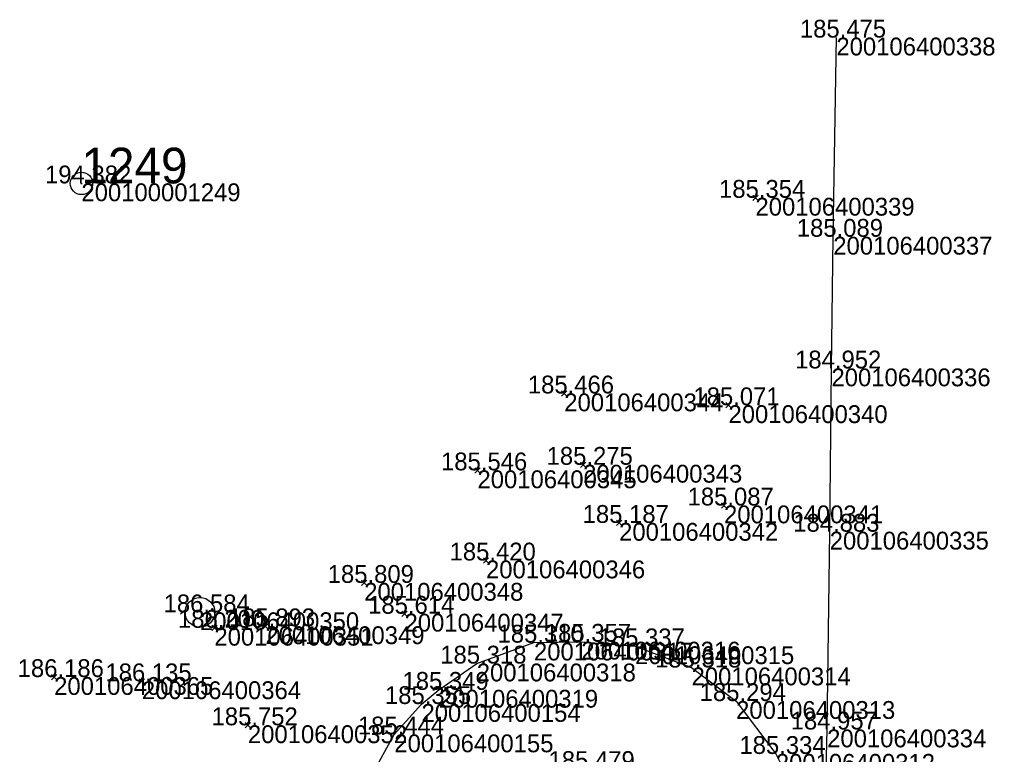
# Model space of a CAD drawing. Extents: x -601392 to -601237, y -1181159 to -1180628.
# Drawn here: x -601309.3 to -601243.7, y -1180894 to -1180844.6 of the extents above; entities that cross this region are included whole.
import ezdxf

# ---------------------------------------------------------------- set-up
doc = ezdxf.new("R2010")
doc.units = 0
for name, color, linetype in [('OMP', 7, 'Continuous'), ('Vrstva 16', 7, 'Continuous'), ('Vrstva 17', 7, 'Continuous'), ('Vrstva 43', 7, 'Continuous'), ('Vrstva 49', 7, 'Continuous'), ('Vrstva 61', 7, 'Continuous'), ('Vzdy červené', 7, 'Continuous')]:
    doc.layers.add(name, color=color, linetype=linetype)

msp = doc.modelspace()

# ---------------------------------------------------------------- linework, layer by layer
at = {"layer": 'OMP'}
for p, q in [((-601254.315, -1180845.801), (-601254.315, -1180845.801)), ((-601305.117, -1180855.611), (-601305.117, -1180855.611)), ((-601259.76, -1180856.581), (-601259.76, -1180856.581)), ((-601254.524, -1180859.204), (-601254.524, -1180859.204)), ((-601254.646, -1180868.066), (-601254.646, -1180868.066)), ((-601272.625, -1180869.748), (-601272.625, -1180869.748)), ((-601261.578, -1180870.541), (-601261.578, -1180870.541)), ((-601271.358, -1180874.549), (-601271.358, -1180874.549)), ((-601278.467, -1180874.924), (-601278.467, -1180874.924)), ((-601261.876, -1180877.287), (-601261.876, -1180877.287)), ((-601268.937, -1180878.459), (-601268.937, -1180878.459)), ((-601254.764, -1180879.051), (-601254.764, -1180879.051)), ((-601277.892, -1180880.989), (-601277.892, -1180880.989)), ((-601286.089, -1180882.496), (-601286.089, -1180882.496)), ((-601297.139, -1180884.477), (-601297.139, -1180884.477)), ((-601283.374, -1180884.571), (-601283.374, -1180884.571)), ((-601296.169, -1180885.517), (-601296.169, -1180885.517)), ((-601292.741, -1180885.417), (-601292.741, -1180885.417)), ((-601274.665, -1180886.517), (-601274.665, -1180886.517)), ((-601271.48, -1180886.455), (-601271.48, -1180886.455)), ((-601267.861, -1180886.763), (-601267.861, -1180886.763)), ((-601278.515, -1180887.924), (-601278.515, -1180887.924)), ((-601264.06, -1180888.189), (-601264.06, -1180888.189)), ((-601306.954, -1180888.833), (-601306.954, -1180888.833)), ((-601301.046, -1180889.118), (-601301.046, -1180889.118)), ((-601281.058, -1180889.692), (-601281.058, -1180889.692)), ((-601261.063, -1180890.448), (-601261.063, -1180890.448)), ((-601282.236, -1180890.646), (-601282.236, -1180890.646)), ((-601293.913, -1180892.078), (-601293.913, -1180892.078)), ((-601254.937, -1180892.361), (-601254.937, -1180892.361)), ((-601284.062, -1180892.694), (-601284.062, -1180892.694)), ((-601258.39, -1180894.006), (-601258.39, -1180894.006))]:
    msp.add_line(p, q, dxfattribs=at)
at = {"layer": 'Vrstva 16'}
msp.add_lwpolyline([(-601285.564, -1180895.44), (-601284.062, -1180892.694), (-601282.236, -1180890.646), (-601281.058, -1180889.692), (-601278.515, -1180887.924), (-601274.665, -1180886.517), (-601271.48, -1180886.455), (-601267.861, -1180886.763), (-601264.06, -1180888.189), (-601261.063, -1180890.448), (-601258.39, -1180894.006), (-601257.215, -1180896.343)], dxfattribs=at)
at = {"layer": 'Vrstva 17'}
msp.add_lwpolyline([(-601255.195, -1180903.174), (-601254.937, -1180892.361), (-601254.764, -1180879.051), (-601254.646, -1180868.066), (-601254.524, -1180859.204), (-601254.315, -1180845.801)], dxfattribs=at)
at = {"layer": 'Vrstva 43'}
msp.add_circle((-601297.139, -1180884.477), 1, dxfattribs=at)
at = {"layer": 'Vrstva 49'}
for p, q in [((-601259.937, -1180856.404), (-601259.583, -1180856.758)), ((-601259.937, -1180856.758), (-601259.583, -1180856.404)), ((-601272.802, -1180869.571), (-601272.448, -1180869.925)), ((-601272.802, -1180869.925), (-601272.448, -1180869.571)), ((-601261.755, -1180870.364), (-601261.401, -1180870.718)), ((-601261.755, -1180870.718), (-601261.401, -1180870.364)), ((-601278.644, -1180874.747), (-601278.29, -1180875.101)), ((-601278.644, -1180875.101), (-601278.29, -1180874.747)), ((-601271.535, -1180874.372), (-601271.181, -1180874.726)), ((-601271.535, -1180874.726), (-601271.181, -1180874.372)), ((-601262.053, -1180877.11), (-601261.699, -1180877.464)), ((-601262.053, -1180877.464), (-601261.699, -1180877.11)), ((-601269.114, -1180878.282), (-601268.76, -1180878.636)), ((-601269.114, -1180878.636), (-601268.76, -1180878.282)), ((-601278.069, -1180880.812), (-601277.715, -1180881.166)), ((-601278.069, -1180881.166), (-601277.715, -1180880.812)), ((-601286.266, -1180882.319), (-601285.912, -1180882.673)), ((-601286.266, -1180882.673), (-601285.912, -1180882.319)), ((-601283.551, -1180884.394), (-601283.197, -1180884.748)), ((-601283.551, -1180884.748), (-601283.197, -1180884.394)), ((-601292.918, -1180885.24), (-601292.564, -1180885.594)), ((-601292.918, -1180885.594), (-601292.564, -1180885.24)), ((-601296.346, -1180885.34), (-601295.992, -1180885.694)), ((-601296.346, -1180885.694), (-601295.992, -1180885.34)), ((-601307.131, -1180888.656), (-601306.777, -1180889.01)), ((-601307.131, -1180889.01), (-601306.777, -1180888.656)), ((-601301.223, -1180888.941), (-601300.869, -1180889.295)), ((-601301.223, -1180889.295), (-601300.869, -1180888.941)), ((-601294.09, -1180891.901), (-601293.736, -1180892.255)), ((-601294.09, -1180892.255), (-601293.736, -1180891.901))]:
    msp.add_line(p, q, dxfattribs=at)
at = {"layer": 'Vzdy červené'}
msp.add_line((-601305.167, -1180855.611), (-601305.067, -1180855.611), dxfattribs=at)
msp.add_circle((-601305.117, -1180855.611), 0.756, dxfattribs=at)

# ---------------------------------------------------------------- texts
at = {"layer": 'OMP'}
for s, p in [('200106400338', (-601254.315, -1180847.001)), ('200100001249', (-601305.117, -1180856.811)), ('200106400339', (-601259.76, -1180857.781)), ('200106400337', (-601254.524, -1180860.404)), ('200106400336', (-601254.646, -1180869.266)), ('200106400344', (-601272.625, -1180870.948)), ('200106400340', (-601261.578, -1180871.741)), ('200106400343', (-601271.358, -1180875.749)), ('200106400345', (-601278.467, -1180876.124)), ('200106400341', (-601261.876, -1180878.487)), ('200106400342', (-601268.937, -1180879.659)), ('200106400335', (-601254.764, -1180880.251)), ('200106400346', (-601277.892, -1180882.189)), ('200106400348', (-601286.089, -1180883.696)), ('200106400350', (-601297.139, -1180885.677)), ('200106400347', (-601283.374, -1180885.771)), ('200106400351', (-601296.169, -1180886.717)), ('200106400349', (-601292.741, -1180886.617)), ('200106400317', (-601274.665, -1180887.717)), ('200106400316', (-601271.48, -1180887.655)), ('200106400315', (-601267.861, -1180887.963)), ('200106400318', (-601278.515, -1180889.124)), ('200106400314', (-601264.06, -1180889.389)), ('200106400365', (-601306.954, -1180890.033)), ('200106400364', (-601301.046, -1180890.318)), ('200106400319', (-601281.058, -1180890.892)), ('200106400313', (-601261.063, -1180891.648)), ('200106400154', (-601282.236, -1180891.846)), ('200106400352', (-601293.913, -1180893.278)), ('200106400334', (-601254.937, -1180893.561)), ('200106400155', (-601284.062, -1180893.894)), ('200106400312', (-601258.39, -1180895.206))]:
    msp.add_text(s, height=1.2, dxfattribs=at).set_placement(p)
at = {"layer": 'Vrstva 61'}
for s, p in [('185.475', (-601256.771, -1180845.801)), ('194.382', (-601307.565, -1180855.611)), ('185.354', (-601262.211, -1180856.581)), ('185.089', (-601256.978, -1180859.204)), ('184.952', (-601257.094, -1180868.066)), ('185.466', (-601275.077, -1180869.748)), ('185.071', (-601263.935, -1180870.541)), ('185.275', (-601273.814, -1180874.549)), ('185.546', (-601280.919, -1180874.924)), ('185.087', (-601264.328, -1180877.287)), ('185.187', (-601271.389, -1180878.459)), ('184.883', (-601257.216, -1180879.051)), ('185.420', (-601280.343, -1180880.989)), ('185.809', (-601288.543, -1180882.496)), ('186.584', (-601299.59, -1180884.477)), ('185.614', (-601285.825, -1180884.571)), ('186.200', (-601298.62, -1180885.517)), ('185.893', (-601295.193, -1180885.417)), ('185.310', (-601277.116, -1180886.517)), ('185.357', (-601273.932, -1180886.455)), ('185.337', (-601270.313, -1180886.763)), ('185.318', (-601280.969, -1180887.924)), ('185.318', (-601266.514, -1180888.189)), ('186.186', (-601309.406, -1180888.833)), ('186.135', (-601303.502, -1180889.118)), ('185.349', (-601283.512, -1180889.692)), ('185.294', (-601263.514, -1180890.448)), ('185.355', (-601284.692, -1180890.646)), ('185.752', (-601296.361, -1180892.078)), ('184.957', (-601257.389, -1180892.361)), ('185.444', (-601286.513, -1180892.694)), ('185.334', (-601260.841, -1180894.006)), ('185.479', (-601273.685, -1180895.02))]:
    msp.add_text(s, height=1.2, dxfattribs=at).set_placement(p)
at = {"layer": 'Vzdy červené'}
msp.add_text('1249', height=2.4, dxfattribs=at).set_placement((-601305.117, -1180855.611))

doc.saveas('drawing.dxf')
